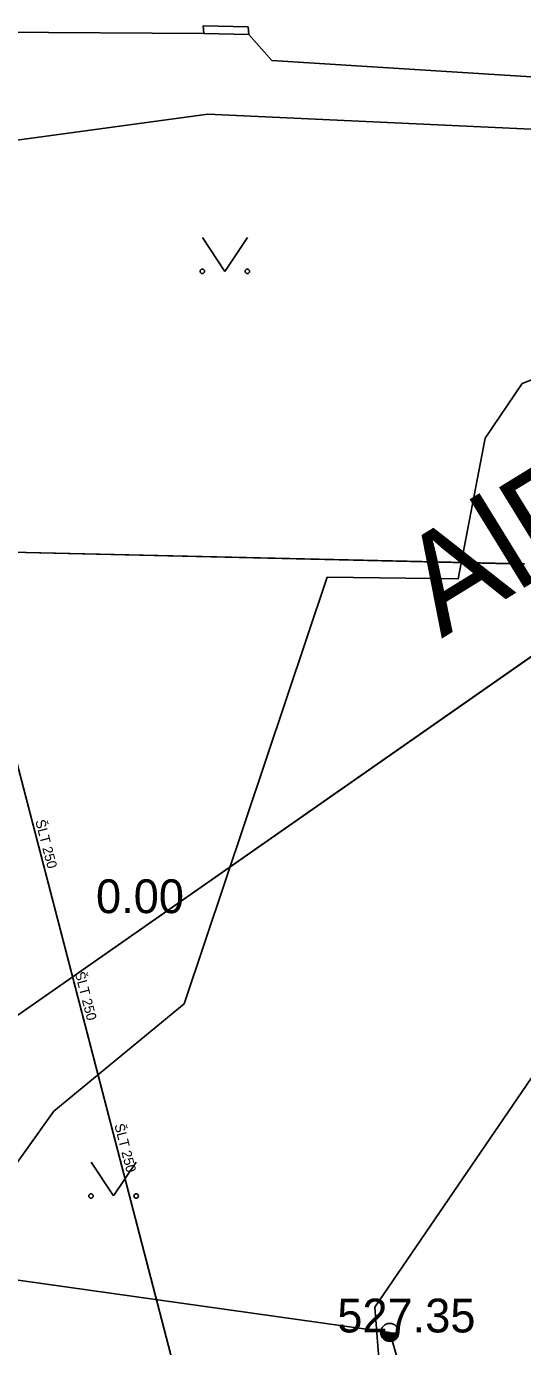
# Model space of a CAD drawing. Extents: x -669393 to -668650, y -1126925 to -1126294.
# Drawn here: x -668970.81 to -668959.79, y -1126829.82 to -1126800.51 of the extents above; entities that cross this region are included whole.
import ezdxf

# ---------------------------------------------------------------- set-up
doc = ezdxf.new("R2010")
doc.units = 0
for name, color, linetype in [('G_Bod_tecka', 7, 'Continuous'), ('G_Bod_vyska', 7, 'Continuous'), ('G_Cesty_Schody', 7, 'Continuous'), ('G_Plochy_zpevnene', 7, 'Continuous'), ('G_Site-Sloupy', 7, 'Continuous'), ('G_Z_ELsilove_nadz_kotovane', 7, 'Continuous'), ('G_Z_ELsilove_podz_kotovane', 7, 'Continuous'), ('G_Z_KANAL_podz_priblizne', 7, 'Continuous'), ('G_Z_SPOJE_podz_kotovane', 7, 'Continuous'), ('G_Z_VODA_podz_kotovane', 7, 'Continuous'), ('G_Zelen-okraj', 7, 'Continuous'), ('G_Zelen-rozhrani', 7, 'Continuous'), ('G_Zelen-Znacky', 7, 'Continuous'), ('Vrstva 18', 7, 'Continuous'), ('Vrstva 25', 7, 'Continuous'), ('Vrstva 3', 7, 'Continuous'), ('Vrstva 4', 7, 'Continuous'), ('Vrstva 62', 7, 'Continuous')]:
    doc.layers.add(name, color=color, linetype=linetype)

msp = doc.modelspace()

# ---------------------------------------------------------------- linework, layer by layer
at = {"layer": 'G_Bod_tecka'}
for p, q in [((-668968.48, -1126820.2), (-668968.48, -1126820.2)), ((-668962.74, -1126829.51), (-668962.74, -1126829.51))]:
    msp.add_line(p, q, dxfattribs=at)
at = {"layer": 'G_Cesty_Schody'}
msp.add_lwpolyline([(-668965.88, -1126800.52), (-668966.88, -1126800.5), (-668966.87, -1126800.67)], dxfattribs=at)
at = {"layer": 'G_Plochy_zpevnene'}
for p, q in [((-668965.88, -1126800.52), (-668965.87, -1126800.69)), ((-668966.87, -1126800.67), (-668975.27, -1126800.61)), ((-668965.87, -1126800.69), (-668966.87, -1126800.67)), ((-668965.36, -1126801.27), (-668953.88, -1126801.99))]:
    msp.add_line(p, q, dxfattribs=at)
at = {"layer": 'G_Site-Sloupy'}
msp.add_circle((-668962.74, -1126829.51), 0.2, dxfattribs=at)
for radius in [0.18, 0.16, 0.14, 0.12, 0.1, 0.08, 0.06, 0.04, 0.02]:
    msp.add_arc((-668962.74, -1126829.51), radius, 180, 0, dxfattribs=at)
at = {"layer": 'G_Z_ELsilove_nadz_kotovane'}
msp.add_lwpolyline([(-668960.563, -1126861.159), (-668963.068, -1126828.951), (-668947.21, -1126805.73)], dxfattribs=at)
at = {"layer": 'G_Z_ELsilove_podz_kotovane'}
msp.add_lwpolyline([(-668974.29, -1126824.76), (-668947.36, -1126805.96), (-668914.48, -1126818.65)], dxfattribs=at)
at = {"layer": 'G_Z_KANAL_podz_priblizne'}
msp.add_line((-668995.4, -1126811.63), (-668959.75, -1126812.45), dxfattribs=at)
at = {"layer": 'G_Z_SPOJE_podz_kotovane'}
msp.add_lwpolyline([(-668924.36, -1126812.03), (-668938.42, -1126806.85), (-668946.33, -1126804.38), (-668957.53, -1126802.89), (-668966.78, -1126802.46), (-668973.09, -1126803.32), (-668974.32, -1126803.33), (-668975.07, -1126803.24), (-668977.88, -1126793.32), (-668977.43, -1126786.05), (-668976.67, -1126777.26), (-668977.77, -1126776.21), (-668984.34, -1126775.67), (-668984.5, -1126775.61), (-668984.3, -1126774.66), (-668983.37, -1126765.19), (-668982.79, -1126754.31), (-668982.27, -1126747.41), (-668981.26, -1126734.45), (-668980.22, -1126728.6), (-668978.82, -1126715.15)], dxfattribs=at)
at = {"layer": 'G_Z_VODA_podz_kotovane'}
msp.add_lwpolyline([(-668940.882, -1126899.444), (-668941.4, -1126897.94), (-668942.92, -1126895.77), (-668947.1, -1126885.14), (-668950.62, -1126876.07), (-668953.88, -1126867.63), (-668959.78, -1126852.42), (-668962.94, -1126844.26), (-668967.16, -1126831.69), (-668972.14, -1126812.55), (-668972.55, -1126809.24), (-668973.32, -1126807.09), (-668974.62, -1126806.13), (-668977.24, -1126805.18), (-668979.87, -1126804.03), (-668984.25, -1126801.05), (-668984.83, -1126799.68), (-668984.92, -1126799.13)], dxfattribs=at)
at = {"layer": 'G_Zelen-okraj'}
msp.add_line((-668962.74, -1126829.51), (-668973.22, -1126828.04), dxfattribs=at)
msp.add_lwpolyline([(-668953.17, -1126862.74), (-668962.74, -1126829.51)], dxfattribs=at)
at = {"layer": 'G_Zelen-rozhrani'}
for p, q in [((-668965.36, -1126801.27), (-668965.87, -1126800.69)), ((-668967.3, -1126822.21), (-668964.13, -1126812.74))]:
    msp.add_line(p, q, dxfattribs=at)
for points in [[(-668964.13, -1126812.74), (-668961.22, -1126812.78), (-668960.62, -1126809.65), (-668959.8, -1126808.44), (-668958.17, -1126807.81), (-668955.24, -1126807.73)], [(-668973.22, -1126828.04), (-668971.49, -1126826.4), (-668970.2, -1126824.6), (-668967.3, -1126822.21)]]:
    msp.add_lwpolyline(points, dxfattribs=at)
at = {"layer": 'G_Zelen-Znacky'}
for p, q in [((-668966.9, -1126805.2), (-668966.4, -1126805.95)), ((-668966.4, -1126805.95), (-668965.9, -1126805.2)), ((-668969.37, -1126825.73), (-668968.87, -1126826.48)), ((-668968.87, -1126826.48), (-668968.37, -1126825.73))]:
    msp.add_line(p, q, dxfattribs=at)
for centre in [(-668966.9, -1126805.95), (-668965.9, -1126805.95), (-668969.37, -1126826.48), (-668968.37, -1126826.48)]:
    msp.add_circle(centre, 0.05, dxfattribs=at)
at = {"layer": 'Vrstva 18'}
msp.add_line((-668995.402, -1126811.627), (-668959.749, -1126812.446), dxfattribs=at)
at = {"layer": 'Vrstva 25'}
msp.add_lwpolyline([(-668940.886, -1126899.444), (-668941.404, -1126897.941), (-668942.921, -1126895.77), (-668947.1, -1126885.143), (-668950.615, -1126876.071), (-668953.884, -1126867.633), (-668959.781, -1126852.415), (-668962.94, -1126844.261), (-668967.16, -1126831.692), (-668972.142, -1126812.547), (-668972.548, -1126809.24), (-668973.32, -1126807.089), (-668974.621, -1126806.131), (-668977.243, -1126805.178), (-668979.875, -1126804.03), (-668984.254, -1126801.05), (-668984.83, -1126799.681), (-668984.921, -1126799.134)], dxfattribs=at)
at = {"layer": 'Vrstva 62'}
msp.add_line((-668974.29, -1126824.76), (-668947.358, -1126805.955), dxfattribs=at)

# ---------------------------------------------------------------- texts
at = {"layer": 'G_Bod_vyska'}
for s, p in [('0.00', (-668969.26, -1126820.2)), ('527.35', (-668963.904, -1126829.51))]:
    msp.add_text(s, height=0.75, dxfattribs=at).set_placement(p)
at = {"layer": 'Vrstva 3'}
msp.add_text('AlFe 1x16', height=2.1939, rotation=31.6527, dxfattribs=at).set_placement((-668961.589, -1126814.107))
at = {"layer": 'Vrstva 4'}
for rotation, p in [(284.5787, (-668970.61, -1126818.154)), (284.5859, (-668969.732, -1126821.528)), (284.5859, (-668968.855, -1126824.903))]:
    msp.add_text('ŠLT 250', height=0.2194, rotation=rotation, dxfattribs=at).set_placement(p)

doc.saveas('drawing.dxf')
